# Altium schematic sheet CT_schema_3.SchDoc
size 577 x 363 mm
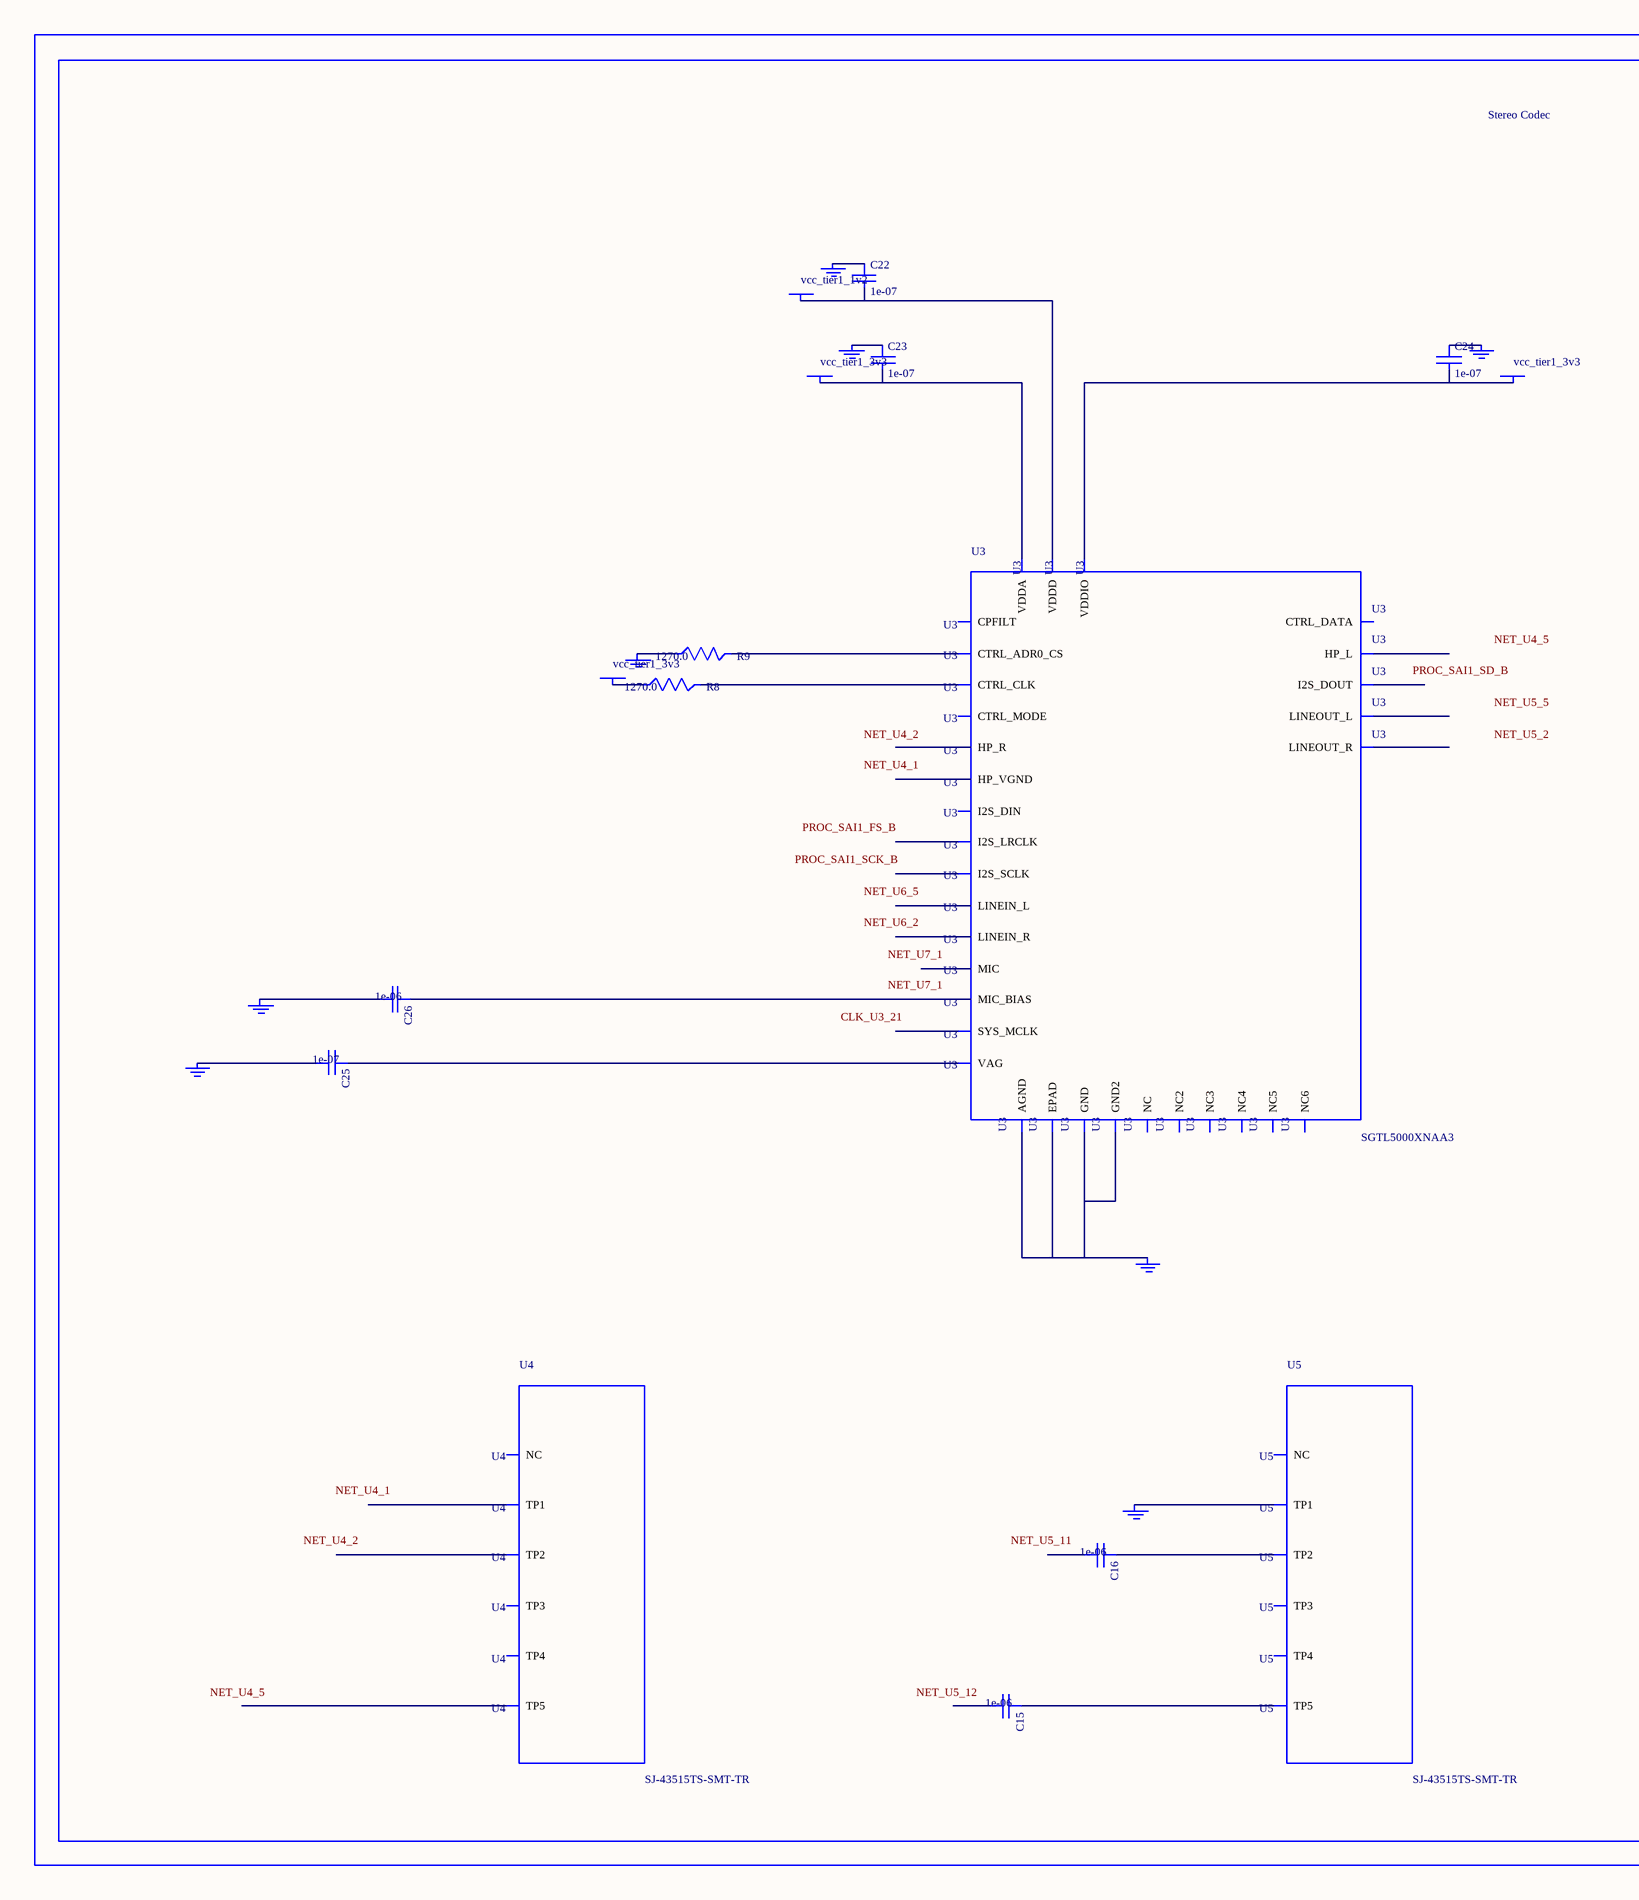
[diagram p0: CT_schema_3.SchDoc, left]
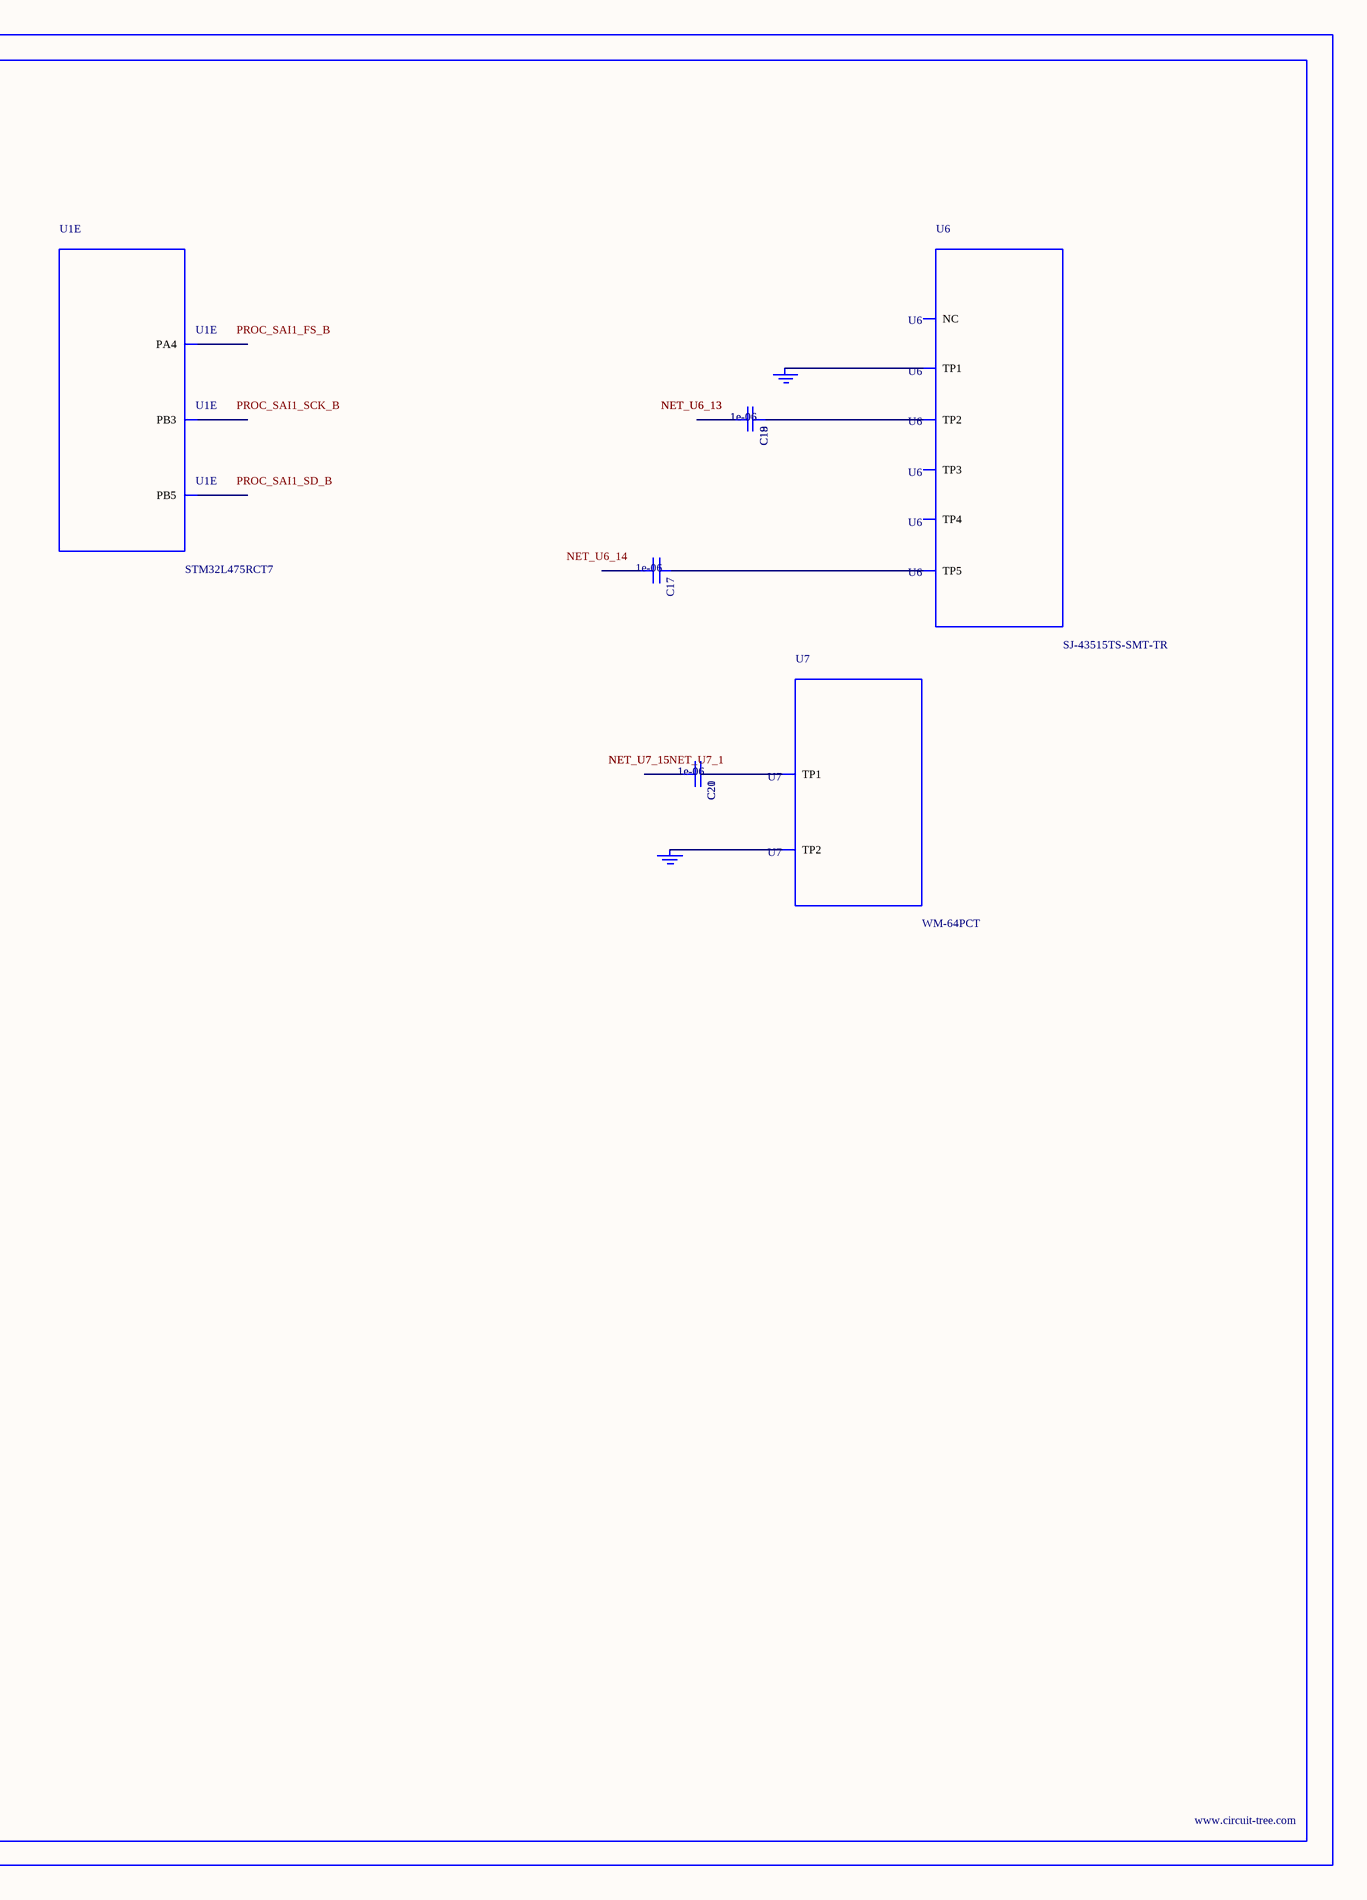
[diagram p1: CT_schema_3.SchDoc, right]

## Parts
BORDER2  (no value)
C15  1e-06  [C0603]
C16  1e-06  [C0603]
C17  1e-06  [C0603]
C18  1e-06  [C0603]
C19  1e-06  [C0603]
C20  1e-06  [C0603]
C21  1e-06  [C0603]
C22  1e-07  [C0402]
C23  1e-07  [C0402]
C24  1e-07  [C0402]
C25  1e-07  [C0402]
C26  1e-06  [C0603]
GND_INSTANCE_2_0  (no value)
GND_INSTANCE_2_1  (no value)
GND_INSTANCE_2_2  (no value)
GND_INSTANCE_2_3  (no value)
GND_INSTANCE_2_4  (no value)
GND_INSTANCE_2_5  (no value)
GND_INSTANCE_2_6  (no value)
GND_INSTANCE_2_7  (no value)
GND_INSTANCE_2_8  (no value)
GND_INSTANCE_2_9  (no value)
GND_INSTANCE_2_10  (no value)
POWER_INSTANCE_2_0  vcc_tier1_3v3
POWER_INSTANCE_2_1  vcc_tier1_3v3
POWER_INSTANCE_2_2  vcc_tier1_3v3
POWER_INSTANCE_2_3  vcc_tier1_1v2
R8  1270.0  [R0603]
R9  1270.0  [R0603]
U1  STM32L475RCT7  [LQFP64]  (part E of 8)
U3  SGTL5000XNAA3  [QFN-32]
U4  SJ-43515TS-SMT-TR  [SJ-43515TS-SMT-TR]
U5  SJ-43515TS-SMT-TR  [SJ-43515TS-SMT-TR]
U6  SJ-43515TS-SMT-TR  [SJ-43515TS-SMT-TR]
U7  WM-64PCT  [WM-64PC]

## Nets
NetC15_1: C15.1 U5.5(TP5)
NetC16_1: C16.1 U5.2(TP2)
NetC17_1: C17.1 U6.5(TP5)
NetC18_1: C18.1 C19.1 U6.2(TP2)
NetC18_2: C18.2 C19.2
NetC20_1: C20.1 C21.1 U7.1(TP1)
NetC20_2: C20.2 C21.2
NetC22_1: C22.1 GND_INSTANCE_2_5.0(GND)
NetC22_2: C22.2 POWER_INSTANCE_2_3.0(PWR) U3.30(VDDD)
NetC23_1: C23.1 GND_INSTANCE_2_1.0(GND)
NetC23_2: C23.2 POWER_INSTANCE_2_0.0(PWR) U3.5(VDDA)
NetC24_1: C24.1 GND_INSTANCE_2_4.0(GND)
NetC24_2: C24.2 POWER_INSTANCE_2_1.0(PWR) U3.20(VDDIO)
NetC25_1: C25.1 U3.10(VAG)
NetC25_2: C25.2 GND_INSTANCE_2_2.0(GND)
NetC26_1: C26.1 U3.16(MIC_BIAS)
NetC26_2: C26.2 GND_INSTANCE_2_3.0(GND)
NetGND_INSTANCE_2_0_0: GND_INSTANCE_2_0.0(GND) U3.1(GND) U3.3(GND2) U3.7(AGND) U3.EXP(EPAD)
NetGND_INSTANCE_2_6_0: GND_INSTANCE_2_6.0(GND) R9.1
NetGND_INSTANCE_2_7_0: GND_INSTANCE_2_7.0(GND) U5.1(TP1)
NetGND_INSTANCE_2_8_0: GND_INSTANCE_2_8.0(GND) GND_INSTANCE_2_9.0(GND) U6.1(TP1)
NetGND_INSTANCE_2_10_0: GND_INSTANCE_2_10.0(GND) U7.2(TP2)
NetPOWER_INSTANCE_2_2_0: POWER_INSTANCE_2_2.0(PWR) R8.1
NetR8_2: R8.2 U3.29(CTRL_CLK)
NetR9_2: R9.2 U3.31(CTRL_ADR0_CS)

Not connected (* = marked no-connect by the designer): C15 2; C16 2; C17 2; U1 20(PA4) 55(PB3) 57(PB5); U3 2(HP_R) 4(HP_VGND) 6(HP_L) 8(NC) 9(NC2) 11(LINEOUT_R) 12(LINEOUT_L) 13(LINEIN_R) 14(LINEIN_L) 15(MIC) 17(NC3) 18(CPFILT) 19(NC4) 21(SYS_MCLK) 22(NC5) 23(I2S_LRCLK) 24(I2S_SCLK) 25(I2S_DOUT) 26(I2S_DIN) 27(CTRL_DATA) 28(NC6) 32(CTRL_MODE); U4 1(TP1) 2(TP2) 3(TP3) 4(TP4) 5(TP5) 6(NC); U5 3(TP3) 4(TP4) 6(NC); U6 3(TP3) 4(TP4) 6(NC)

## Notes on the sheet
- Labels drawn without touching a wire or pin: CLK_U3_21, NET_U4_1, NET_U4_2, NET_U4_5, NET_U5_2, NET_U5_5, NET_U5_11, NET_U5_12, NET_U6_2, NET_U6_5, NET_U6_14, NET_U7_1, PROC_SAI1_FS_B, PROC_SAI1_SCK_B, PROC_SAI1_SD_B

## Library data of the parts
BORDER2 = BORDER_PAGE2
C15-C21 C26 = C0603C105K3RACTU
C22-C25 = C0402C104K3RACTU
GND_INSTANCE_2_0-GND_INSTANCE_2_10 = GND
POWER_INSTANCE_2_0-POWER_INSTANCE_2_3 = PWR
R8 R9 = RC0603FR-071K27L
